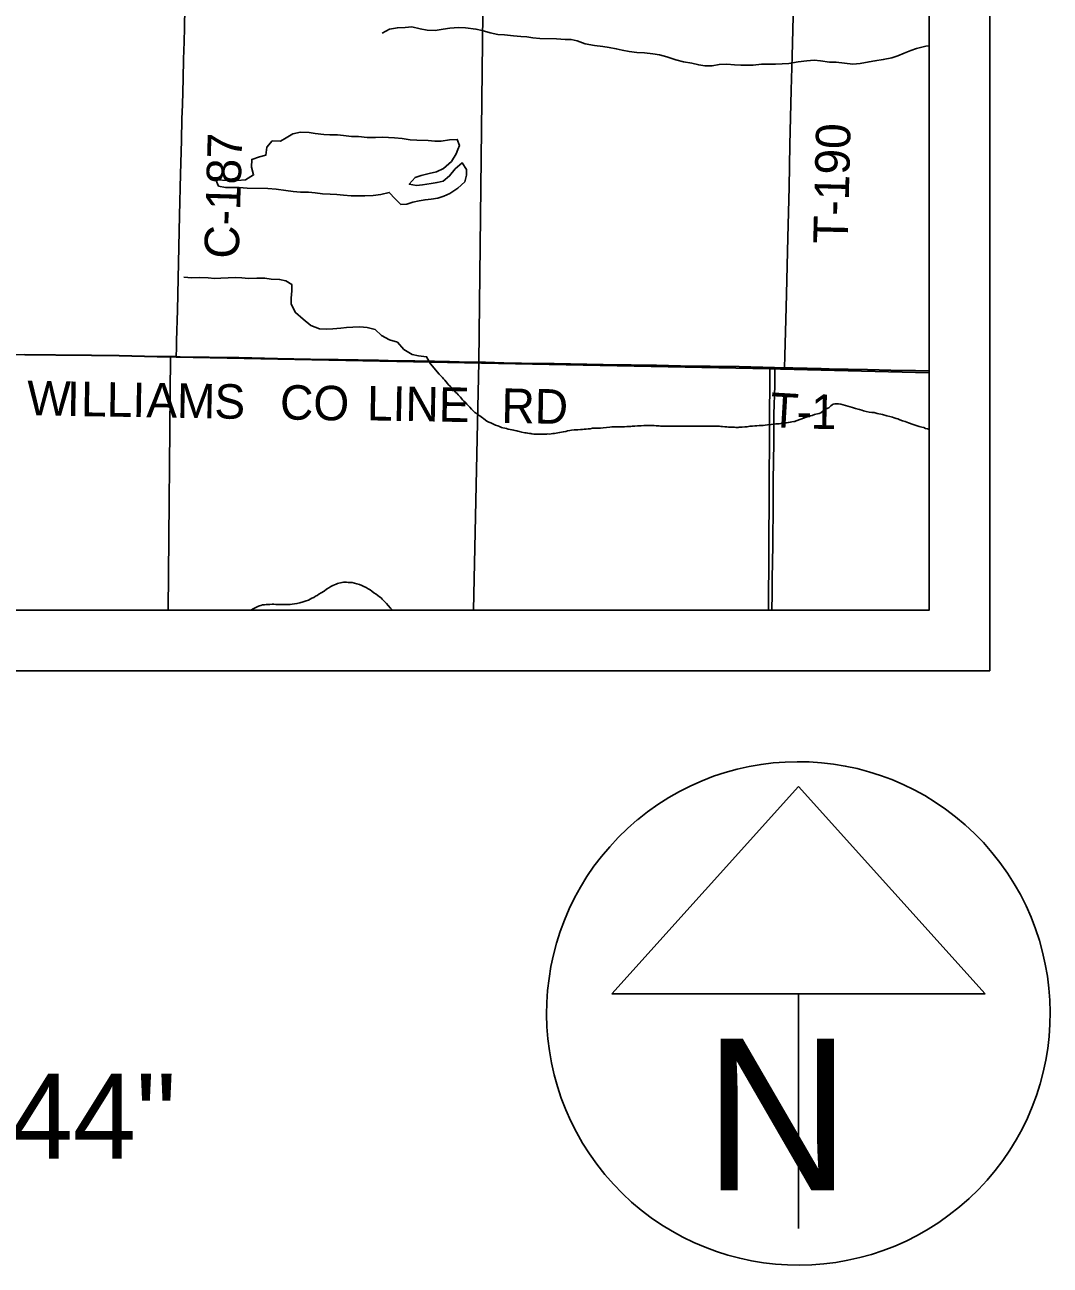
# Model space of a CAD drawing. Extents: x 0 to 34, y 0 to 22.
# Drawn here: x 7.41 to 9.099, y 13.02 to 15.064 of the extents above; entities that cross this region are included whole.
import ezdxf

# ---------------------------------------------------------------- set-up
doc = ezdxf.new("R2010")
doc.units = 0
for name, color, linetype in [('GM_X_Corporation', 7, 'Continuous'), ('GM_X_County_Road', 7, 'Continuous'), ('GM_X_County_Road_Text', 7, 'Continuous'), ('GM_X_Minor_Lake', 7, 'Continuous'), ('GM_X_Minor_River', 7, 'Continuous'), ('GM_X_Rail_Line', 7, 'Continuous'), ('GM_X_Township_Road', 7, 'Continuous'), ('GM_X_Township_Road_Text', 7, 'Continuous'), ('SH_Data', 7, 'Continuous'), ('SH_Text', 7, 'Continuous')]:
    doc.layers.add(name, color=color, linetype=linetype)

msp = doc.modelspace()

# ---------------------------------------------------------------- linework, layer by layer
at = {"layer": 'GM_X_Corporation'}
for points in [[(7.4098, 14.5209), (7.4608, 14.5206), (7.5199, 14.5198), (7.5653, 14.5192), (7.628, 14.5179), (7.6588, 14.5175), (7.666, 14.5174), (7.7139, 14.5166), (7.7406, 14.5161), (7.7624, 14.5159), (7.8264, 14.5147), (7.8805, 14.5136), (7.9265, 14.5129), (7.993, 14.5115), (8.0086, 14.5111), (8.0278, 14.5108), (8.0527, 14.5104), (8.085, 14.5098), (8.1099, 14.5093), (8.1416, 14.5086), (8.169, 14.5082), (8.1994, 14.5074), (8.2286, 14.507), (8.2821, 14.5063), (8.3629, 14.5046), (8.4089, 14.5039), (8.4506, 14.5034), (8.4904, 14.5026), (8.5389, 14.5019), (8.5868, 14.501), (8.6454, 14.4994), (8.6614, 14.4991), (8.6756, 14.4989), (8.6992, 14.4984), (8.7222, 14.4978), (8.7353, 14.4975), (8.7981, 14.4962), (8.8366, 14.4953), (8.8776, 14.4948), (8.9, 14.4942), (8.9, 20.9)], [(7.4098, 14.5209), (7.4608, 14.5206), (7.5199, 14.5198), (7.5653, 14.5192), (7.628, 14.5179), (7.6588, 14.5175), (7.666, 14.5174), (7.7139, 14.5166), (7.7406, 14.5161), (7.7624, 14.5159), (7.8264, 14.5147), (7.8805, 14.5136), (7.9265, 14.5129), (7.993, 14.5115), (8.0086, 14.5111), (8.0278, 14.5108), (8.0527, 14.5104), (8.085, 14.5098), (8.1099, 14.5093), (8.1416, 14.5086), (8.169, 14.5082), (8.1994, 14.5074), (8.2286, 14.507), (8.2821, 14.5063), (8.3629, 14.5046), (8.4089, 14.5039), (8.4506, 14.5034), (8.4904, 14.5026), (8.5389, 14.5019), (8.5868, 14.501), (8.6454, 14.4994), (8.6614, 14.4991), (8.6756, 14.4989), (8.6992, 14.4984), (8.7222, 14.4978), (8.7353, 14.4975), (8.7981, 14.4962), (8.8366, 14.4953), (8.8776, 14.4948), (8.9, 14.4942), (8.9, 20.5041)], [(2.1, 14.1), (8.9, 14.1), (8.9, 14.4942), (8.8776, 14.4948), (8.8366, 14.4953), (8.7981, 14.4962), (8.7353, 14.4975), (8.7222, 14.4978), (8.6992, 14.4984), (8.6756, 14.4989), (8.6614, 14.4991), (8.6454, 14.4994), (8.5868, 14.501), (8.5389, 14.5019), (8.4904, 14.5026), (8.4506, 14.5034), (8.4089, 14.5039), (8.3629, 14.5046), (8.2821, 14.5063), (8.2286, 14.507), (8.1994, 14.5074), (8.169, 14.5082), (8.1416, 14.5086), (8.1099, 14.5093), (8.085, 14.5098), (8.0527, 14.5104), (8.0278, 14.5108), (8.0086, 14.5111), (7.993, 14.5115), (7.9265, 14.5129), (7.8805, 14.5136), (7.8264, 14.5147), (7.7624, 14.5159), (7.7406, 14.5161), (7.7139, 14.5166), (7.666, 14.5174), (7.6588, 14.5175), (7.628, 14.5179), (7.5653, 14.5192), (7.5199, 14.5198), (7.4608, 14.5206), (7.4098, 14.5209)], [(5.7036, 14.1), (8.9, 14.1), (8.9, 14.4942), (8.8776, 14.4948), (8.8366, 14.4953), (8.7981, 14.4962), (8.7353, 14.4975), (8.7222, 14.4978), (8.6992, 14.4984), (8.6756, 14.4989), (8.6614, 14.4991), (8.6454, 14.4994), (8.5868, 14.501), (8.5389, 14.5019), (8.4904, 14.5026), (8.4506, 14.5034), (8.4089, 14.5039), (8.3629, 14.5046), (8.2821, 14.5063), (8.2286, 14.507), (8.1994, 14.5074), (8.169, 14.5082), (8.1416, 14.5086), (8.1099, 14.5093), (8.085, 14.5098), (8.0527, 14.5104), (8.0278, 14.5108), (8.0086, 14.5111), (7.993, 14.5115), (7.9265, 14.5129), (7.8805, 14.5136), (7.8264, 14.5147), (7.7624, 14.5159), (7.7406, 14.5161), (7.7139, 14.5166), (7.666, 14.5174), (7.6588, 14.5175), (7.628, 14.5179), (7.5653, 14.5192), (7.5199, 14.5198), (7.4608, 14.5206), (7.4098, 14.5209)]]:
    msp.add_lwpolyline(points, dxfattribs=at)
for points in [[(7.646, 14.1), (8.6351, 14.1), (8.6372, 14.4974), (7.6593, 14.5168), (7.6499, 14.517)], [(8.6351, 14.1), (8.9, 14.1), (8.9, 14.4908), (8.655, 14.4971), (8.6372, 14.4974)]]:
    msp.add_lwpolyline(points, close=True, dxfattribs=at)
at = {"layer": 'GM_X_County_Road'}
msp.add_line((8.6456, 14.4988), (8.6616, 14.4986), dxfattribs=at)
for points in [[(7.6591, 14.517), (7.6593, 14.5181), (7.6595, 14.5199), (7.6597, 14.5232), (7.6599, 14.5267), (7.6602, 14.5435), (7.6616, 14.5939), (7.6627, 14.6461), (7.6651, 14.7499), (7.6667, 14.8183), (7.6682, 14.8736), (7.669, 14.9096), (7.6698, 14.9326), (7.6709, 14.9755), (7.6717, 15.0078), (7.6724, 15.0364), (7.673, 15.0594), (7.6744, 15.1272)], [(6.917, 14.5273), (6.9444, 14.5271), (6.9904, 14.5263), (7.1234, 14.5241), (7.1688, 14.5235), (7.1924, 14.5231), (7.2154, 14.5226), (7.2353, 14.5224), (7.2608, 14.5221), (7.3081, 14.5215), (7.3696, 14.5211), (7.41, 14.5203), (7.461, 14.5201), (7.5201, 14.5192), (7.5655, 14.5187), (7.6283, 14.5174), (7.6591, 14.517)], [(7.6591, 14.517), (7.6662, 14.5169), (7.7141, 14.5161), (7.7408, 14.5156), (7.7626, 14.5154), (7.8266, 14.5141), (7.8807, 14.5131), (7.9267, 14.5123), (7.9933, 14.511), (8.0088, 14.5106), (8.0281, 14.5102), (8.0529, 14.5099), (8.0853, 14.5093), (8.1101, 14.5088), (8.1418, 14.508), (8.1692, 14.5076), (8.1997, 14.5069), (8.2289, 14.5064), (8.2824, 14.5057), (8.3632, 14.5041), (8.4092, 14.5034), (8.4508, 14.5029), (8.4906, 14.502), (8.5391, 14.5013), (8.587, 14.5005), (8.6456, 14.4988)], [(8.6409, 14.1), (8.6412, 14.1268), (8.6415, 14.1516), (8.6422, 14.207), (8.643, 14.276), (8.6432, 14.312), (8.6435, 14.3462), (8.6439, 14.3742), (8.6442, 14.4227), (8.6455, 14.4701), (8.6455, 14.4858), (8.6456, 14.4988)]]:
    msp.add_lwpolyline(points, dxfattribs=at)
at = {"layer": 'GM_X_Minor_Lake'}
for points in [[(8.1235, 14.8588), (8.1261, 14.8655), (8.1225, 14.8754), (8.1099, 14.8745), (8.0959, 14.8725), (8.0856, 14.8727), (8.0747, 14.8737), (8.0557, 14.874), (8.0451, 14.875), (8.0319, 14.8771), (8.019, 14.8782), (8.0092, 14.8787), (7.9989, 14.8789), (7.9879, 14.8784), (7.9739, 14.8786), (7.9599, 14.8801), (7.9481, 14.8803), (7.9353, 14.882), (7.9251, 14.883), (7.9125, 14.8829), (7.9027, 14.8834), (7.8883, 14.8852), (7.8785, 14.8866), (7.8645, 14.8876), (7.8515, 14.8844), (7.8408, 14.8782), (7.8312, 14.8727), (7.8176, 14.873), (7.809, 14.8625), (7.8072, 14.8496), (7.7966, 14.8468), (7.784, 14.8425), (7.7833, 14.8296), (7.7869, 14.817), (7.7738, 14.8089), (7.7598, 14.8077), (7.7461, 14.808), (7.7249, 14.8091)], [(7.7249, 14.8091), (7.7293, 14.7984), (7.7406, 14.7963), (7.7531, 14.7964), (7.763, 14.7963), (7.7766, 14.7952), (7.8107, 14.7946), (7.8244, 14.7932), (7.8399, 14.791), (7.852, 14.7896), (7.8645, 14.7886), (7.8777, 14.7884), (7.8883, 14.7874), (7.9004, 14.786), (7.9133, 14.785), (7.9243, 14.7844), (7.9353, 14.7834), (7.9478, 14.7824), (7.9576, 14.7826), (7.9705, 14.7824), (7.9842, 14.7829), (7.9967, 14.7849), (8.0104, 14.7881), (8.0201, 14.7773), (8.0298, 14.768), (8.0396, 14.7689), (8.0492, 14.7721), (8.0595, 14.7742), (8.0694, 14.7759), (8.0796, 14.7772), (8.0903, 14.7786), (8.1006, 14.7818), (8.1105, 14.7861), (8.1236, 14.795), (8.1348, 14.8058), (8.1376, 14.8163), (8.1378, 14.8258), (8.1308, 14.8366), (8.1193, 14.8269), (8.1099, 14.8153), (8.0991, 14.8064), (8.0893, 14.8047), (8.0797, 14.803), (8.0653, 14.8007), (8.0554, 14.7993), (8.0433, 14.8015), (8.0534, 14.8126), (8.0629, 14.8162), (8.0763, 14.8194), (8.0884, 14.8218), (8.0999, 14.8273), (8.1131, 14.8392), (8.1209, 14.8519), (8.1235, 14.8588)]]:
    msp.add_lwpolyline(points, dxfattribs=at)
at = {"layer": 'GM_X_Minor_River'}
msp.add_line((8.0124, 14.1033), (8.0156, 14.1), dxfattribs=at)
for points in [[(8.9, 15.0296), (8.8945, 15.0292), (8.8792, 15.0253), (8.8697, 15.0217), (8.859, 15.0178), (8.8483, 15.013), (8.8384, 15.0098), (8.8243, 15.0071), (8.8106, 15.0047), (8.8011, 15.0033), (8.7862, 15.0006), (8.7741, 14.9993), (8.7468, 15.0029), (8.7358, 15.0027), (8.7207, 15.0049), (8.7105, 15.0058), (8.6983, 15.0049), (8.6839, 15.003), (8.6687, 15.0006), (8.6577, 14.9997), (8.6467, 14.9995), (8.6349, 14.9993), (8.6239, 14.9992), (8.6098, 14.9979), (8.6, 14.9977), (8.5897, 14.9976), (8.5791, 14.9985), (8.5666, 14.9992), (8.5541, 14.999), (8.5423, 14.9966), (8.5306, 14.9968), (8.5204, 14.9981), (8.509, 15.001), (8.495, 15.0032), (8.4826, 15.0068), (8.4679, 15.0113), (8.4558, 15.0146), (8.4445, 15.0163), (8.4309, 15.0181), (8.4184, 15.0187), (8.4059, 15.0205), (8.3942, 15.0226), (8.3844, 15.0247), (8.3726, 15.0268), (8.3621, 15.0285), (8.3488, 15.0303), (8.3333, 15.0329), (8.3202, 15.038), (8.31, 15.0401), (8.3001, 15.0403), (8.2861, 15.0414), (8.2588, 15.0419), (8.2471, 15.0429), (8.2369, 15.0446), (8.227, 15.0452), (8.2153, 15.0461), (8.2001, 15.0476), (8.1892, 15.0485), (8.1767, 15.0511), (8.1635, 15.0547), (8.1533, 15.0572), (8.1359, 15.0591), (8.1245, 15.0597), (8.1101, 15.0588), (8.0991, 15.0571), (8.0861, 15.0551), (8.0729, 15.0557), (8.0612, 15.0578), (8.0476, 15.0608), (8.0366, 15.0598), (8.024, 15.0593), (8.0107, 15.0569), (7.9988, 15.0507)], [(8.0787, 14.5057), (8.0719, 14.5172), (8.0587, 14.519), (8.0485, 14.5211), (8.0346, 14.5293), (8.0239, 14.5413), (8.0111, 14.5453), (7.9979, 14.5524), (7.9875, 14.5621), (7.9743, 14.5654), (7.9618, 14.5667), (7.9504, 14.5658), (7.9402, 14.5656), (7.9306, 14.5643), (7.9174, 14.5631), (7.9079, 14.5625), (7.8957, 14.5631), (7.8811, 14.5687), (7.8688, 14.5795), (7.8561, 14.59), (7.8491, 14.6038), (7.8489, 14.6137), (7.8499, 14.6262), (7.8498, 14.6364), (7.84, 14.6423), (7.8298, 14.6448), (7.8162, 14.645), (7.8056, 14.6468), (7.7923, 14.6466), (7.7787, 14.6465), (7.7677, 14.6475), (7.7578, 14.6481), (7.7453, 14.6475), (7.7328, 14.6466), (7.7225, 14.6461), (7.7119, 14.6471), (7.6975, 14.6481), (7.6854, 14.6476), (7.6718, 14.6486)], [(8.0786, 14.5057), (8.0929, 14.4885), (8.0947, 14.4866), (8.0981, 14.4834), (8.0999, 14.4811), (8.1021, 14.4788), (8.1043, 14.4761), (8.1062, 14.4734), (8.108, 14.4711), (8.111, 14.4687), (8.114, 14.4656), (8.1202, 14.4586), (8.1221, 14.4567), (8.1239, 14.4547), (8.1258, 14.4528), (8.1276, 14.4505), (8.1295, 14.4485), (8.1313, 14.4466), (8.1336, 14.4442), (8.1354, 14.4423), (8.1384, 14.4392), (8.1414, 14.4361), (8.1432, 14.4341), (8.1462, 14.431), (8.1495, 14.4275), (8.1517, 14.4252), (8.1551, 14.4232), (8.1573, 14.4213), (8.1599, 14.4197), (8.1618, 14.4181), (8.1641, 14.4166), (8.1659, 14.4154), (8.1693, 14.413), (8.1715, 14.4114), (8.1745, 14.4098), (8.1779, 14.4082), (8.1824, 14.4062), (8.1854, 14.4047), (8.1892, 14.4034), (8.1922, 14.4022), (8.1952, 14.401), (8.1978, 14.4002), (8.2009, 14.3994), (8.2035, 14.3989), (8.2065, 14.3981), (8.2095, 14.3976), (8.2129, 14.3968), (8.2152, 14.3964), (8.2175, 14.3959), (8.2205, 14.3951), (8.2224, 14.3947), (8.2246, 14.3942), (8.2269, 14.3934), (8.2288, 14.393), (8.2341, 14.3921), (8.236, 14.3917), (8.2386, 14.3912), (8.2416, 14.3908), (8.2435, 14.3907), (8.2454, 14.3903), (8.2485, 14.3899), (8.2511, 14.3898), (8.2549, 14.3897), (8.2576, 14.39), (8.2606, 14.39), (8.2629, 14.3899), (8.2648, 14.3899), (8.2671, 14.3898), (8.2697, 14.3897), (8.2716, 14.3901), (8.2739, 14.39), (8.2773, 14.3903), (8.28, 14.3906), (8.2827, 14.391), (8.2857, 14.3916), (8.2884, 14.392), (8.291, 14.3923), (8.2941, 14.393), (8.2975, 14.3937), (8.3013, 14.3943), (8.3044, 14.395), (8.3078, 14.3957), (8.3109, 14.3964), (8.3151, 14.3967), (8.3177, 14.397), (8.3211, 14.3969), (8.3253, 14.3972), (8.3287, 14.3975), (8.3318, 14.3978), (8.3348, 14.3981), (8.3383, 14.3984), (8.3417, 14.3987), (8.3455, 14.3994), (8.3497, 14.3996), (8.3542, 14.3995), (8.3584, 14.3998), (8.363, 14.4001), (8.374, 14.4013), (8.3771, 14.4016), (8.379, 14.4016), (8.3812, 14.4016)], [(8.7135, 14.4226), (8.7162, 14.4233), (8.7185, 14.424), (8.7216, 14.425), (8.7278, 14.4306), (8.7328, 14.4328), (8.7347, 14.4331), (8.7382, 14.4364), (8.7401, 14.4379), (8.742, 14.439), (8.7447, 14.4397), (8.7477, 14.44), (8.7508, 14.4396), (8.7545, 14.4391), (8.7734, 14.4337), (8.7787, 14.4321), (8.7828, 14.4308), (8.7851, 14.4304), (8.7889, 14.4292), (8.7919, 14.4283), (8.7964, 14.4271), (8.8009, 14.4262), (8.8055, 14.4257), (8.8096, 14.4252), (8.8145, 14.4236), (8.8232, 14.4219), (8.83, 14.4198), (8.8353, 14.4186), (8.8395, 14.4177), (8.8425, 14.4165), (8.8455, 14.4157), (8.8481, 14.4148), (8.8515, 14.4136), (8.856, 14.412), (8.8605, 14.4104), (8.8658, 14.4083), (8.8734, 14.4059), (8.8786, 14.4042), (8.8835, 14.4026), (8.8877, 14.4014), (8.8911, 14.4005), (8.8941, 14.3993), (8.8971, 14.3985), (8.8997, 14.3977), (8.9, 14.3975)], [(8.3812, 14.4016), (8.3843, 14.4019), (8.3869, 14.4018), (8.3896, 14.4021), (8.3938, 14.402), (8.3964, 14.402), (8.3983, 14.4019), (8.4017, 14.4022), (8.404, 14.4022), (8.4063, 14.4025), (8.4086, 14.4024), (8.4109, 14.4027), (8.4151, 14.403), (8.4196, 14.4033), (8.4257, 14.4035), (8.4299, 14.4038), (8.4341, 14.4041), (8.4375, 14.404), (8.4409, 14.4039), (8.4439, 14.4042), (8.447, 14.4042), (8.45, 14.4037), (8.4527, 14.4037), (8.4549, 14.4036), (8.4572, 14.4032), (8.4599, 14.4031), (8.4636, 14.403), (8.4659, 14.403), (8.4682, 14.4029), (8.4709, 14.4029), (8.4739, 14.4028), (8.4769, 14.4031), (8.4811, 14.403), (8.4853, 14.4029), (8.4883, 14.4032), (8.491, 14.4031), (8.4933, 14.4031), (8.4963, 14.403), (8.5005, 14.4029), (8.5047, 14.4032), (8.5073, 14.4031), (8.5122, 14.403), (8.5149, 14.403), (8.5244, 14.4031), (8.5289, 14.403), (8.5327, 14.4029), (8.5365, 14.4032), (8.5396, 14.4031), (8.5426, 14.4031), (8.546, 14.403), (8.5494, 14.4029), (8.5521, 14.4028), (8.5548, 14.4028), (8.557, 14.4023), (8.5593, 14.4023), (8.5631, 14.4018), (8.5665, 14.4017), (8.5695, 14.4013), (8.5726, 14.4012), (8.576, 14.4011), (8.579, 14.4011), (8.5813, 14.401), (8.5832, 14.401), (8.5851, 14.4009), (8.587, 14.4013), (8.5893, 14.4012), (8.5919, 14.4015), (8.5965, 14.4018), (8.6003, 14.4021), (8.6045, 14.4027), (8.6087, 14.403), (8.6125, 14.4033), (8.6163, 14.4036), (8.6197, 14.4039), (8.6231, 14.4042), (8.6265, 14.4041), (8.6296, 14.4044), (8.6338, 14.4051), (8.6399, 14.4057), (8.644, 14.406), (8.6475, 14.4067), (8.6501, 14.4066), (8.6528, 14.4069), (8.6555, 14.4072), (8.6585, 14.4079), (8.6619, 14.4082), (8.665, 14.4085), (8.668, 14.4092), (8.6711, 14.4095), (8.6738, 14.4102), (8.6768, 14.4105), (8.6787, 14.4109), (8.6806, 14.4116), (8.6887, 14.4144), (8.6929, 14.4162), (8.6975, 14.4176), (8.7017, 14.4191), (8.7047, 14.4197), (8.707, 14.4205), (8.7109, 14.4219), (8.7135, 14.4226)], [(7.7823, 14.1), (7.7834, 14.1004), (7.7853, 14.1015), (7.7876, 14.1025), (7.7896, 14.1036), (7.7919, 14.1047), (7.7949, 14.1065), (7.7969, 14.1069), (7.7988, 14.1076), (7.8018, 14.1083), (7.8049, 14.1086), (7.8079, 14.1089), (7.811, 14.1092), (7.814, 14.1091), (7.8174, 14.1094), (7.8205, 14.1094), (7.8235, 14.1089), (7.8269, 14.1092), (7.8299, 14.1091), (7.8326, 14.1091), (7.8356, 14.109), (7.8394, 14.1089), (7.8417, 14.1089), (7.8444, 14.1092), (7.8474, 14.1091), (7.8504, 14.1094), (7.8543, 14.1101), (7.8584, 14.1107), (7.8634, 14.1118), (7.8688, 14.1135), (7.8734, 14.115), (7.8772, 14.1164), (7.8803, 14.1178), (7.883, 14.1197), (7.886, 14.1207), (7.8887, 14.1226), (7.8918, 14.124), (7.8945, 14.1259), (7.8983, 14.1284), (7.903, 14.1313), (7.9072, 14.1343), (7.9111, 14.1365), (7.9145, 14.1387), (7.9176, 14.1405), (7.9203, 14.1416), (7.923, 14.1427), (7.9253, 14.1437), (7.9276, 14.1444), (7.9329, 14.1455), (7.9352, 14.1458), (7.9375, 14.1457), (7.9398, 14.1457), (7.9428, 14.1456), (7.9466, 14.1455), (7.9496, 14.1451), (7.953, 14.1442), (7.9572, 14.1434), (7.9613, 14.1421), (7.9654, 14.1405), (7.9688, 14.1389), (7.9726, 14.1369), (7.9759, 14.1349), (7.9793, 14.133), (7.9819, 14.131), (7.9849, 14.1283), (7.989, 14.1263), (7.9916, 14.1239), (7.9946, 14.122), (7.9969, 14.12), (7.9987, 14.1181), (8.0009, 14.1157), (8.0032, 14.1134), (8.0057, 14.1107), (8.0087, 14.1072), (8.0124, 14.1033)]]:
    msp.add_lwpolyline(points, dxfattribs=at)
at = {"layer": 'GM_X_Rail_Line'}
for points in [[(8.1578, 14.5086), (8.1698, 15.5158), (8.179, 16.303), (8.179, 16.3934), (8.1652, 16.4746), (8.1423, 16.5389), (8.1055, 16.594), (8.0627, 16.6538), (7.9876, 16.735), (7.8453, 16.8958), (7.7917, 16.9478), (7.7304, 16.9923), (7.6677, 17.0229), (7.5972, 17.0673), (7.5441, 17.1046)], [(8.1491, 14.1), (8.1561, 14.4085), (8.1578, 14.5086)]]:
    msp.add_lwpolyline(points, dxfattribs=at)
at = {"layer": 'GM_X_Township_Road'}
msp.add_line((8.6456, 14.4988), (8.6616, 14.4986), dxfattribs=at)
for points in [[(8.6616, 14.4986), (8.6623, 14.5194), (8.6639, 14.5783), (8.6649, 14.6206), (8.6669, 14.7138), (8.6691, 14.7965), (8.6705, 14.8667), (8.6728, 14.9568), (8.6745, 15.0128), (8.6759, 15.078), (8.677, 15.1203), (8.6787, 15.1918), (8.6798, 15.2353), (8.6804, 15.2614), (8.6811, 15.2937), (8.6825, 15.3378), (8.684, 15.3857), (8.6853, 15.4522), (8.6859, 15.4708), (8.6864, 15.4914), (8.6865, 15.5008), (8.6867, 15.5074)], [(6.917, 14.5273), (6.9444, 14.5271), (6.9904, 14.5263), (7.1234, 14.5241), (7.1688, 14.5235), (7.1924, 14.5231), (7.2154, 14.5226), (7.2353, 14.5224), (7.2608, 14.5221), (7.3081, 14.5215), (7.3696, 14.5211), (7.41, 14.5203), (7.461, 14.5201), (7.5201, 14.5192), (7.5655, 14.5187), (7.6283, 14.5174), (7.6591, 14.517)], [(7.6591, 14.517), (7.6662, 14.5169), (7.7141, 14.5161), (7.7408, 14.5156), (7.7626, 14.5154), (7.8266, 14.5141), (7.8807, 14.5131), (7.9267, 14.5123), (7.9933, 14.511), (8.0088, 14.5106), (8.0281, 14.5102), (8.0529, 14.5099), (8.0853, 14.5093), (8.1101, 14.5088), (8.1418, 14.508), (8.1692, 14.5076), (8.1997, 14.5069), (8.2289, 14.5064), (8.2824, 14.5057), (8.3632, 14.5041), (8.4092, 14.5034), (8.4508, 14.5029), (8.4906, 14.502), (8.5391, 14.5013), (8.587, 14.5005), (8.6456, 14.4988)], [(8.6616, 14.4986), (8.6758, 14.4983), (8.6995, 14.4978), (8.7225, 14.4973), (8.7355, 14.4969), (8.7983, 14.4957), (8.8368, 14.4948), (8.8778, 14.4942), (8.9, 14.4937)]]:
    msp.add_lwpolyline(points, dxfattribs=at)
at = {"layer": 'SH_Data'}
for p, q in [((9, 21), (9, 14)), ((8.9, 20.9), (8.9, 14.1)), ((2.1, 14.1), (8.9, 14.1)), ((2, 14), (9, 14)), ((8.6845, 13.809), (8.3769, 13.4678)), ((8.9921, 13.4678), (8.6845, 13.809)), ((8.3769, 13.4678), (8.9921, 13.4678)), ((8.6845, 13.4678), (8.6845, 13.081)), ((8.6845, 13.4353), (8.6845, 13.4353)), ((8.6845, 13.4353), (8.6845, 13.4353))]:
    msp.add_line(p, q, dxfattribs=at)
msp.add_arc((8.6845, 13.4353), 0.4148, 129.7798, 129.7633, dxfattribs=at)

# ---------------------------------------------------------------- texts
at = {"layer": 'GM_X_County_Road_Text'}
for s, height, rotation, p in [('C-187', 0.05682, 88.3514, (7.7624, 14.6783)), ('W', 0.0568, 359.0215, (7.4135, 14.421)), ('I', 0.0568, 359.02, (7.479, 14.4199)), ('L', 0.0568, 359.0164, (7.5022, 14.4195)), ('L', 0.0568, 359.0124, (7.5446, 14.4188)), ('I', 0.0568, 359.0079, (7.587, 14.4181)), ('A', 0.0568, 359.0041, (7.6101, 14.4177)), ('M', 0.0568, 359.0021, (7.6602, 14.4168)), ('S', 0.0568, 359.0001, (7.722, 14.4157)), ('CO', 0.05682, 358.9728, (7.8301, 14.4141)), ('LINE', 0.05682, 358.9728, (7.9734, 14.4126)), ('RD', 0.05682, 358.9728, (8.1949, 14.4085))]:
    msp.add_text(s, height=height, rotation=rotation, dxfattribs=at).set_placement(p)
at = {"layer": 'GM_X_Township_Road_Text'}
for s, height, rotation, p in [('T-190', 0.05682, 88.5877, (8.7657, 14.7029)), ('T', 0.0568, 356.6639, (8.6365, 14.4019)), ('1', 0.0568, 358.8548, (8.7046, 14.3988)), ('-', 0.0568, 358.7076, (8.6811, 14.3993))]:
    msp.add_text(s, height=height, rotation=rotation, dxfattribs=at).set_placement(p)
at = {"layer": 'SH_Data'}
msp.add_text('N', height=0.25, dxfattribs=at).set_placement((8.5292, 13.1439))
at = {"layer": 'SH_Text'}
msp.add_text('LATITUDE:  N 41°26\'29"     LONGITUDE:  W 84°35\'44"', height=0.14, dxfattribs=at).set_placement((3.071, 13.1958))

doc.saveas('drawing.dxf')
